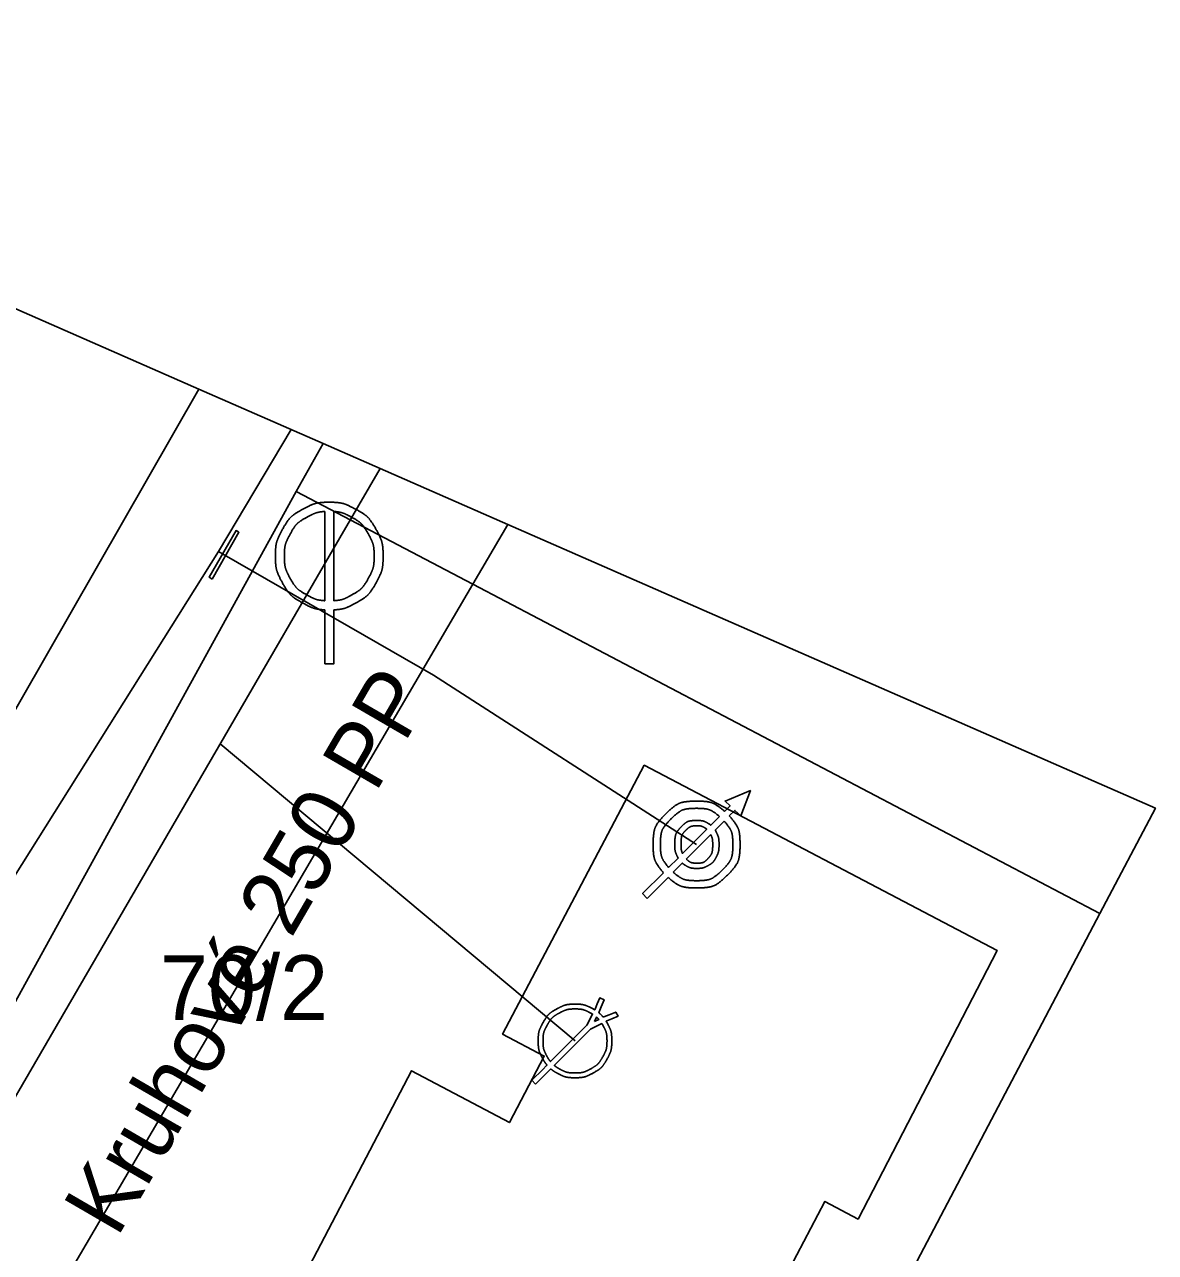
# Model space of a CAD drawing. Extents: x -559654 to -559448, y -1076607 to -1076478.
# Drawn here: x -559474.44 to -559448.2, y -1076562.77 to -1076534.29 of the extents above; entities that cross this region are included whole.
import ezdxf

# ---------------------------------------------------------------- set-up
doc = ezdxf.new("R2010")
doc.units = 0
for name, color, linetype in [('Armatura vodovodní', 7, 'Continuous'), ('Default', 7, 'Continuous'), ('Kanalizační přípojka', 7, 'Continuous'), ('Kanalizační stoka', 7, 'Continuous'), ('Kanalizační šachta', 7, 'Continuous'), ('Odběrné místo', 7, 'Continuous'), ('Odběrné místo na kanalizaci', 7, 'Continuous'), ('Parcela-polygon', 7, 'Continuous'), ('Parcela-text', 7, 'Continuous'), ('Popis kmenové stoky', 7, 'Continuous'), ('Vodovodní přípojka', 7, 'Continuous'), ('Vodovodní řad', 7, 'Continuous')]:
    doc.layers.add(name, color=color, linetype=linetype)

msp = doc.modelspace()

# ---------------------------------------------------------------- linework, layer by layer
at = {"layer": 'Armatura vodovodní'}
msp.add_lwpolyline([(-559470.088, -1076547.151), (-559469.465, -1076546.067), (-559469.533, -1076546.028), (-559470.156, -1076547.112)], close=True, dxfattribs=at)
at = {"layer": 'Default'}
for points in [[(-559467.985, -1076545.531), (-559468.184, -1076545.639), (-559468.339, -1076545.792), (-559468.452, -1076545.993)], [(-559467.37, -1076545.37), (-559467.582, -1076545.37), (-559467.787, -1076545.424), (-559467.985, -1076545.531)], [(-559466.756, -1076545.531), (-559466.955, -1076545.424), (-559467.16, -1076545.37), (-559467.37, -1076545.37)], [(-559466.288, -1076545.993), (-559466.401, -1076545.792), (-559466.557, -1076545.639), (-559466.756, -1076545.531)], [(-559468.273, -1076546.099), (-559468.181, -1076545.932), (-559468.051, -1076545.804), (-559467.885, -1076545.714)], [(-559467.885, -1076545.714), (-559467.742, -1076545.638), (-559467.604, -1076545.594), (-559467.473, -1076545.582)], [(-559467.267, -1076545.582), (-559467.136, -1076545.594), (-559466.999, -1076545.638), (-559466.857, -1076545.714)], [(-559466.857, -1076545.714), (-559466.691, -1076545.804), (-559466.561, -1076545.932), (-559466.468, -1076546.099)], [(-559468.452, -1076545.993), (-559468.564, -1076546.193), (-559468.62, -1076546.402), (-559468.62, -1076546.62)], [(-559468.412, -1076546.62), (-559468.412, -1076546.439), (-559468.366, -1076546.266), (-559468.273, -1076546.099)], [(-559466.468, -1076546.099), (-559466.374, -1076546.266), (-559466.328, -1076546.439), (-559466.328, -1076546.62)], [(-559466.12, -1076546.62), (-559466.12, -1076546.402), (-559466.176, -1076546.193), (-559466.288, -1076545.993)], [(-559468.62, -1076546.62), (-559468.62, -1076546.836), (-559468.565, -1076547.044), (-559468.455, -1076547.243)], [(-559468.276, -1076547.138), (-559468.367, -1076546.973), (-559468.412, -1076546.801), (-559468.412, -1076546.62)], [(-559466.328, -1076546.62), (-559466.328, -1076546.801), (-559466.373, -1076546.973), (-559466.464, -1076547.138)], [(-559466.285, -1076547.243), (-559466.175, -1076547.044), (-559466.12, -1076546.836), (-559466.12, -1076546.62)], [(-559468.455, -1076547.243), (-559468.345, -1076547.441), (-559468.191, -1076547.595), (-559467.993, -1076547.704)], [(-559467.89, -1076547.521), (-559468.056, -1076547.43), (-559468.185, -1076547.302), (-559468.276, -1076547.138)], [(-559466.464, -1076547.138), (-559466.555, -1076547.302), (-559466.683, -1076547.43), (-559466.848, -1076547.521)], [(-559466.747, -1076547.704), (-559466.549, -1076547.595), (-559466.395, -1076547.441), (-559466.285, -1076547.243)], [(-559467.473, -1076547.655), (-559467.609, -1076547.645), (-559467.748, -1076547.601), (-559467.89, -1076547.521)], [(-559466.848, -1076547.521), (-559466.991, -1076547.601), (-559467.131, -1076547.645), (-559467.267, -1076547.655)], [(-559467.993, -1076547.704), (-559467.818, -1076547.802), (-559467.645, -1076547.856), (-559467.473, -1076547.868)], [(-559467.267, -1076547.868), (-559467.095, -1076547.856), (-559466.922, -1076547.802), (-559466.747, -1076547.704)], [(-559458.845, -1076552.304), (-559459.124, -1076552.304), (-559459.363, -1076552.402), (-559459.559, -1076552.599)], [(-559458.195, -1076552.541), (-559458.379, -1076552.383), (-559458.596, -1076552.304), (-559458.845, -1076552.304)], [(-559459.559, -1076552.599), (-559459.756, -1076552.795), (-559459.855, -1076553.033), (-559459.855, -1076553.311)], [(-559459.44, -1076552.717), (-559459.276, -1076552.553), (-559459.078, -1076552.471), (-559458.845, -1076552.471)], [(-559458.845, -1076552.471), (-559458.642, -1076552.471), (-559458.464, -1076552.534), (-559458.313, -1076552.66)], [(-559457.837, -1076553.311), (-559457.837, -1076553.056), (-559457.92, -1076552.834), (-559458.087, -1076552.647)], [(-559459.686, -1076553.311), (-559459.686, -1076553.079), (-559459.604, -1076552.881), (-559459.44, -1076552.717)], [(-559459.209, -1076552.905), (-559459.305, -1076553.005), (-559459.353, -1076553.145), (-559459.353, -1076553.323)], [(-559458.838, -1076552.753), (-559458.989, -1076552.753), (-559459.113, -1076552.804), (-559459.209, -1076552.905)], [(-559459.097, -1076552.98), (-559459.025, -1076552.911), (-559458.938, -1076552.876), (-559458.838, -1076552.876)], [(-559458.571, -1076552.824), (-559458.65, -1076552.777), (-559458.74, -1076552.753), (-559458.838, -1076552.753)], [(-559458.838, -1076552.876), (-559458.767, -1076552.876), (-559458.703, -1076552.894), (-559458.646, -1076552.93)], [(-559458.646, -1076552.93), (-559458.633, -1076552.938), (-559458.621, -1076552.947), (-559458.61, -1076552.957)], [(-559458.516, -1076552.863), (-559458.533, -1076552.849), (-559458.551, -1076552.836), (-559458.571, -1076552.824)], [(-559458.206, -1076552.767), (-559458.071, -1076552.92), (-559458.004, -1076553.102), (-559458.004, -1076553.311)], [(-559459.207, -1076553.326), (-559459.207, -1076553.164), (-559459.17, -1076553.048), (-559459.097, -1076552.98)], [(-559458.517, -1076553.079), (-559458.517, -1076553.08), (-559458.517, -1076553.081), (-559458.516, -1076553.082)], [(-559458.516, -1076553.082), (-559458.486, -1076553.147), (-559458.472, -1076553.223), (-559458.472, -1076553.31)], [(-559458.388, -1076553.023), (-559458.396, -1076553.007), (-559458.405, -1076552.991), (-559458.414, -1076552.975)], [(-559458.325, -1076553.311), (-559458.325, -1076553.204), (-559458.346, -1076553.108), (-559458.388, -1076553.023)], [(-559459.855, -1076553.311), (-559459.855, -1076553.562), (-559459.775, -1076553.779), (-559459.614, -1076553.964)], [(-559459.495, -1076553.845), (-559459.623, -1076553.693), (-559459.686, -1076553.515), (-559459.686, -1076553.311)], [(-559459.353, -1076553.323), (-559459.353, -1076553.418), (-559459.332, -1076553.507), (-559459.291, -1076553.592)], [(-559459.173, -1076553.521), (-559459.195, -1076553.465), (-559459.207, -1076553.4), (-559459.207, -1076553.326)], [(-559458.472, -1076553.31), (-559458.472, -1076553.448), (-559458.506, -1076553.555), (-559458.576, -1076553.63)], [(-559458.391, -1076553.603), (-559458.347, -1076553.518), (-559458.325, -1076553.42), (-559458.325, -1076553.311)], [(-559458.004, -1076553.311), (-559458.004, -1076553.543), (-559458.086, -1076553.741), (-559458.251, -1076553.904)], [(-559458.132, -1076554.023), (-559457.936, -1076553.827), (-559457.837, -1076553.589), (-559457.837, -1076553.311)], [(-559459.291, -1076553.592), (-559459.286, -1076553.602), (-559459.281, -1076553.613), (-559459.275, -1076553.624)], [(-559459.179, -1076553.742), (-559459.157, -1076553.76), (-559459.135, -1076553.777), (-559459.11, -1076553.792)], [(-559459.11, -1076553.792), (-559459.03, -1076553.841), (-559458.94, -1076553.865), (-559458.839, -1076553.865)], [(-559458.84, -1076553.743), (-559458.937, -1076553.743), (-559459.019, -1076553.711), (-559459.086, -1076553.648)], [(-559458.576, -1076553.63), (-559458.645, -1076553.706), (-559458.733, -1076553.743), (-559458.84, -1076553.743)], [(-559458.839, -1076553.865), (-559458.746, -1076553.865), (-559458.659, -1076553.843), (-559458.578, -1076553.799)], [(-559458.578, -1076553.799), (-559458.497, -1076553.754), (-559458.435, -1076553.689), (-559458.391, -1076553.603)], [(-559459.508, -1076554.072), (-559459.322, -1076554.236), (-559459.101, -1076554.318), (-559458.845, -1076554.318)], [(-559458.845, -1076554.15), (-559459.055, -1076554.15), (-559459.236, -1076554.084), (-559459.389, -1076553.952)], [(-559458.251, -1076553.904), (-559458.415, -1076554.068), (-559458.613, -1076554.15), (-559458.845, -1076554.15)], [(-559458.845, -1076554.318), (-559458.567, -1076554.318), (-559458.329, -1076554.22), (-559458.132, -1076554.023)], [(-559462.088, -1076557.123), (-559462.224, -1076557.197), (-559462.331, -1076557.302), (-559462.407, -1076557.439)], [(-559462.31, -1076557.495), (-559462.244, -1076557.376), (-559462.151, -1076557.285), (-559462.033, -1076557.221)], [(-559461.667, -1076557.013), (-559461.812, -1076557.013), (-559461.952, -1076557.05), (-559462.088, -1076557.123)], [(-559462.033, -1076557.221), (-559461.914, -1076557.157), (-559461.792, -1076557.125), (-559461.667, -1076557.125)], [(-559461.249, -1076557.123), (-559461.385, -1076557.05), (-559461.524, -1076557.013), (-559461.667, -1076557.013)], [(-559461.667, -1076557.125), (-559461.543, -1076557.125), (-559461.422, -1076557.157), (-559461.303, -1076557.221)], [(-559461.303, -1076557.221), (-559461.289, -1076557.229), (-559461.275, -1076557.237), (-559461.261, -1076557.245)], [(-559461.21, -1076557.146), (-559461.223, -1076557.138), (-559461.236, -1076557.131), (-559461.249, -1076557.123)], [(-559461.013, -1076557.316), (-559461.044, -1076557.278), (-559461.079, -1076557.244), (-559461.116, -1076557.213)], [(-559462.407, -1076557.439), (-559462.484, -1076557.576), (-559462.522, -1076557.719), (-559462.522, -1076557.868)], [(-559462.41, -1076557.868), (-559462.41, -1076557.739), (-559462.376, -1076557.615), (-559462.31, -1076557.495)], [(-559461.167, -1076557.317), (-559461.15, -1076557.332), (-559461.133, -1076557.349), (-559461.117, -1076557.367)], [(-559461.046, -1076557.46), (-559461.039, -1076557.471), (-559461.032, -1076557.483), (-559461.025, -1076557.495)], [(-559461.025, -1076557.495), (-559460.959, -1076557.615), (-559460.925, -1076557.739), (-559460.925, -1076557.868)], [(-559460.928, -1076557.439), (-559460.935, -1076557.428), (-559460.941, -1076557.418), (-559460.947, -1076557.409)], [(-559460.813, -1076557.868), (-559460.813, -1076557.719), (-559460.851, -1076557.576), (-559460.928, -1076557.439)], [(-559462.522, -1076557.868), (-559462.522, -1076558.016), (-559462.484, -1076558.158), (-559462.409, -1076558.293)], [(-559462.311, -1076558.237), (-559462.377, -1076558.119), (-559462.41, -1076557.996), (-559462.41, -1076557.868)], [(-559460.925, -1076557.868), (-559460.925, -1076557.996), (-559460.958, -1076558.12), (-559461.023, -1076558.237)], [(-559460.926, -1076558.293), (-559460.851, -1076558.158), (-559460.813, -1076558.016), (-559460.813, -1076557.868)], [(-559462.409, -1076558.293), (-559462.382, -1076558.342), (-559462.351, -1076558.387), (-559462.317, -1076558.428)], [(-559462.236, -1076558.347), (-559462.264, -1076558.313), (-559462.29, -1076558.276), (-559462.311, -1076558.237)], [(-559461.023, -1076558.237), (-559461.089, -1076558.355), (-559461.181, -1076558.446), (-559461.298, -1076558.512)], [(-559461.242, -1076558.609), (-559461.106, -1076558.534), (-559461.001, -1076558.429), (-559460.926, -1076558.293)], [(-559462.229, -1076558.516), (-559462.187, -1076558.551), (-559462.142, -1076558.582), (-559462.092, -1076558.609)], [(-559462.037, -1076558.511), (-559462.077, -1076558.489), (-559462.114, -1076558.464), (-559462.148, -1076558.435)], [(-559462.092, -1076558.609), (-559461.957, -1076558.684), (-559461.815, -1076558.722), (-559461.667, -1076558.722)], [(-559461.667, -1076558.61), (-559461.796, -1076558.61), (-559461.919, -1076558.577), (-559462.037, -1076558.511)], [(-559461.298, -1076558.512), (-559461.416, -1076558.577), (-559461.539, -1076558.61), (-559461.667, -1076558.61)], [(-559461.667, -1076558.722), (-559461.52, -1076558.722), (-559461.378, -1076558.684), (-559461.242, -1076558.609)]]:
    msp.add_open_spline(points, degree=2, dxfattribs=at)
at = {"layer": 'Kanalizační přípojka'}
msp.add_lwpolyline([(-559461.667, -1076557.868), (-559469.9, -1076550.975)], dxfattribs=at)
at = {"layer": 'Kanalizační stoka'}
msp.add_lwpolyline([(-559466.186, -1076544.589), (-559467.37, -1076546.62), (-559483.9, -1076575.08), (-559500.698, -1076566.177)], dxfattribs=at)
at = {"layer": 'Kanalizační šachta'}
for points in [[(-559467.473, -1076545.582), (-559467.473, -1076547.655)], [(-559467.267, -1076547.655), (-559467.267, -1076545.582)], [(-559467.473, -1076549.12), (-559467.267, -1076549.12), (-559467.267, -1076547.868)], [(-559467.473, -1076547.868), (-559467.473, -1076549.12)]]:
    msp.add_lwpolyline(points, dxfattribs=at)
at = {"layer": 'Odběrné místo'}
for points in [[(-559458.087, -1076552.647), (-559457.957, -1076552.518), (-559457.82, -1076552.647), (-559457.598, -1076552.061), (-559458.185, -1076552.302), (-559458.067, -1076552.413), (-559458.195, -1076552.541)], [(-559458.313, -1076552.66), (-559458.516, -1076552.863)], [(-559458.61, -1076552.957), (-559459.173, -1076553.521)], [(-559458.414, -1076552.975), (-559458.206, -1076552.767)], [(-559459.086, -1076553.648), (-559458.517, -1076553.079)], [(-559459.275, -1076553.624), (-559459.495, -1076553.845)], [(-559459.389, -1076553.952), (-559459.179, -1076553.742)], [(-559459.614, -1076553.964), (-559460.098, -1076554.449), (-559459.996, -1076554.561)], [(-559459.996, -1076554.561), (-559459.508, -1076554.072)]]:
    msp.add_lwpolyline(points, dxfattribs=at)
at = {"layer": 'Odběrné místo na kanalizaci'}
for points in [[(-559461.116, -1076557.213), (-559461.107, -1076557.195), (-559461.059, -1076557.075), (-559460.994, -1076556.913), (-559461.094, -1076556.868), (-559461.155, -1076557.009), (-559461.201, -1076557.127), (-559461.21, -1076557.146)], [(-559460.947, -1076557.409), (-559460.928, -1076557.399), (-559460.81, -1076557.354), (-559460.668, -1076557.292), (-559460.724, -1076557.198), (-559460.875, -1076557.259), (-559460.996, -1076557.307), (-559461.013, -1076557.316)], [(-559461.261, -1076557.245), (-559461.393, -1076557.503), (-559462.236, -1076558.347)], [(-559462.148, -1076558.435), (-559461.307, -1076557.594), (-559461.046, -1076557.46)], [(-559461.215, -1076557.415), (-559461.167, -1076557.317)], [(-559461.117, -1076557.367), (-559461.215, -1076557.415)], [(-559462.317, -1076558.428), (-559462.329, -1076558.44), (-559462.418, -1076558.529), (-559462.67, -1076558.78), (-559462.583, -1076558.869)], [(-559462.583, -1076558.869), (-559462.331, -1076558.618), (-559462.241, -1076558.528), (-559462.229, -1076558.516)]]:
    msp.add_lwpolyline(points, dxfattribs=at)
at = {"layer": 'Parcela-polygon'}
for p, q in [((-559470.396, -1076542.745), (-559475.677, -1076540.432)), ((-559467.515, -1076544.007), (-559470.396, -1076542.745)), ((-559463.228, -1076545.885), (-559467.515, -1076544.007)), ((-559454.441, -1076564.319), (-559449.485, -1076554.911))]:
    msp.add_line(p, q, dxfattribs=at)
for points in [[(-559489.702, -1076534.288), (-559496.26, -1076546.97), (-559502.55, -1076559.13), (-559485.32, -1076568.19), (-559478.68, -1076557.2), (-559470.396, -1076542.745)], [(-559470.396, -1076542.745), (-559478.68, -1076557.2), (-559485.32, -1076568.19), (-559489.07, -1076574.14), (-559500.912, -1076594.458)], [(-559497.784, -1076596.071), (-559493.23, -1076588.57), (-559485.49, -1076575.98), (-559482.14, -1076570.54), (-559468.14, -1076545.12), (-559467.515, -1076544.007)], [(-559467.515, -1076544.007), (-559468.14, -1076545.12), (-559464.04, -1076547.27), (-559463.228, -1076545.885)], [(-559463.228, -1076545.885), (-559464.04, -1076547.27), (-559449.485, -1076554.911)], [(-559449.485, -1076554.911), (-559448.198, -1076552.468), (-559463.228, -1076545.885)], [(-559449.485, -1076554.911), (-559464.04, -1076547.27), (-559476.74, -1076568.93), (-559461.138, -1076577.031)], [(-559454.441, -1076564.319), (-559456.68, -1076563.14), (-559455.87, -1076561.59), (-559455.1, -1076562), (-559451.87, -1076555.77), (-559460.06, -1076551.47), (-559463.35, -1076557.71), (-559462.38, -1076558.22), (-559463.19, -1076559.76), (-559465.46, -1076558.56), (-559470.02, -1076567.27), (-559459.042, -1076573.053)], [(-559459.042, -1076573.053), (-559470.02, -1076567.27), (-559465.46, -1076558.56), (-559463.19, -1076559.76), (-559462.38, -1076558.22), (-559463.35, -1076557.71), (-559460.06, -1076551.47), (-559451.87, -1076555.77), (-559455.1, -1076562), (-559455.87, -1076561.59), (-559456.68, -1076563.14), (-559454.441, -1076564.319)]]:
    msp.add_lwpolyline(points, dxfattribs=at)
msp.add_lwpolyline([(-559476.74, -1076568.93), (-559481.94, -1076577.8), (-559485.49, -1076575.98), (-559482.14, -1076570.54), (-559468.14, -1076545.12), (-559464.04, -1076547.27)], close=True, dxfattribs=at)
at = {"layer": 'Vodovodní přípojka'}
msp.add_lwpolyline([(-559458.848, -1076553.311), (-559464.952, -1076549.384), (-559469.81, -1076546.59), (-559469.94, -1076546.51)], dxfattribs=at)
at = {"layer": 'Vodovodní řad'}
msp.add_lwpolyline([(-559486.082, -1076571.032), (-559485.727, -1076571.286), (-559485.591, -1076571.397), (-559469.94, -1076546.51), (-559468.257, -1076543.682)], dxfattribs=at)

# ---------------------------------------------------------------- texts
at = {"layer": 'Parcela-text'}
msp.add_text('70/2', height=1.5, dxfattribs=at).set_placement((-559471.3, -1076557.38))
at = {"layer": 'Popis kmenové stoky'}
msp.add_text('Kruhové 250 PP', height=1.5, rotation=59.8513, dxfattribs=at).set_placement((-559472.292, -1076562.453))

doc.saveas('drawing.dxf')
